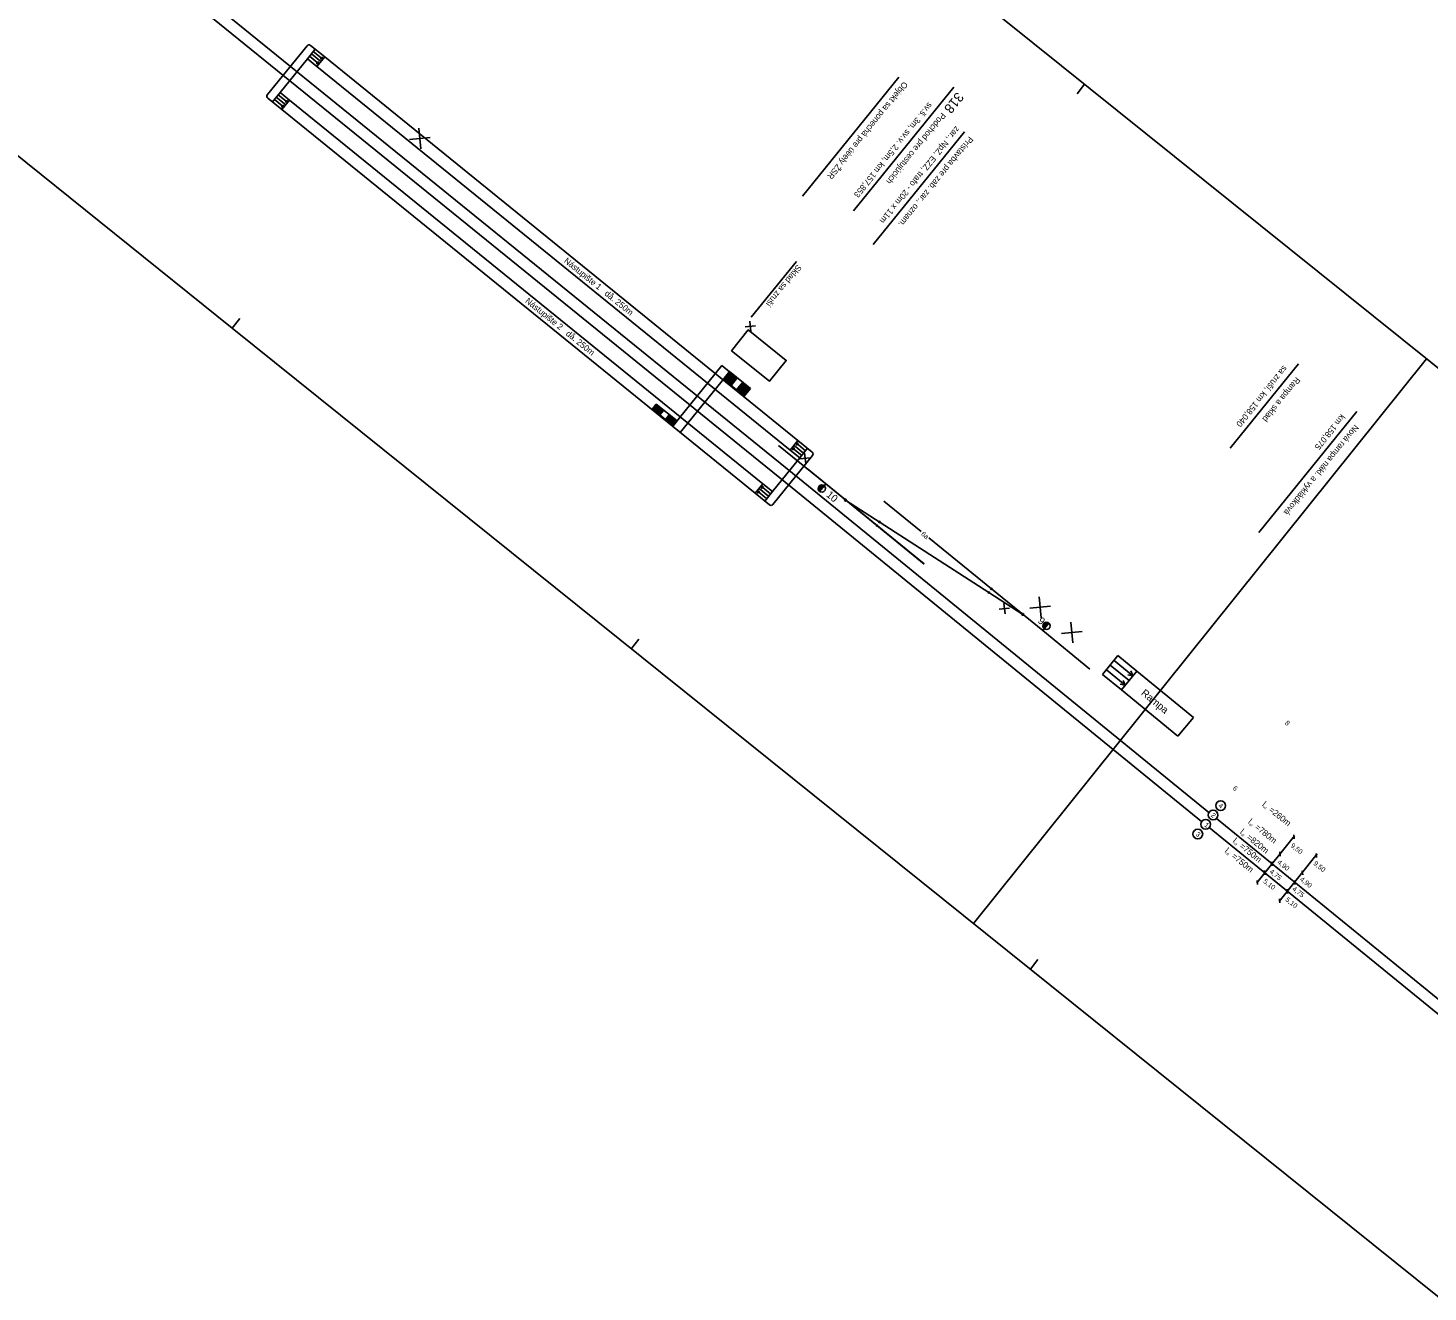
# Model space of a CAD drawing. Extents: x -486838 to -485015, y -1312876 to -1311330.
# Drawn here: x -486431 to -485856, y -1312351 to -1311833 of the extents above; entities that cross this region are included whole.
import ezdxf

# ---------------------------------------------------------------- set-up
doc = ezdxf.new("R2010")
doc.units = 0
for name, color, linetype in [('kolaj s', 7, 'Continuous'), ('Level 61', 7, 'Continuous'), ('popis 25', 7, 'Continuous'), ('popis 35', 7, 'Continuous'), ('stavby', 7, 'Continuous')]:
    doc.layers.add(name, color=color, linetype=linetype)

msp = doc.modelspace()

# ---------------------------------------------------------------- linework, layer by layer
at = {"layer": 'kolaj s'}
for p, q in [((-486420.89, -1311775.01), (-486117.19, -1312021.16)), ((-486417.9, -1311771.32), (-486114.2, -1312017.47)), ((-486122.79, -1312003.76), (-486103.41, -1312019.55)), ((-486110.85, -1312013.35), (-486062.97, -1312052.36)), ((-486117.2, -1312021.15), (-485949.13, -1312158.08)), ((-486114.2, -1312017.47), (-485946.15, -1312154.38)), ((-486103.41, -1312019.55), (-486082.37, -1312036.69)), ((-486095.25, -1312026.2), (-486095.25, -1312026.2)), ((-486095.25, -1312026.2), (-486036.48, -1312064.12)), ((-486079.6, -1312026.61), (-486064.23, -1312039.13)), ((-486082.05, -1312036.3), (-486082.69, -1312037.08)), ((-486082.37, -1312036.69), (-486082.37, -1312036.69)), ((-486082.37, -1312036.69), (-486063.03, -1312052.45)), ((-486081.02, -1312034.78), (-486081.56, -1312035.62)), ((-486081.29, -1312035.2), (-486081.29, -1312035.2)), ((-486061.14, -1312041.65), (-486035.39, -1312062.63)), ((-486035.71, -1312063.02), (-486035.08, -1312062.24)), ((-486014.35, -1312079.77), (-486035.39, -1312062.63)), ((-486035.39, -1312062.63), (-486035.39, -1312062.63)), ((-486036.75, -1312064.54), (-486036.2, -1312063.7)), ((-486022.51, -1312073.13), (-486036.48, -1312064.12)), ((-486036.48, -1312064.12), (-486036.48, -1312064.12)), ((-486022.51, -1312073.13), (-486022.51, -1312073.13)), ((-486014.35, -1312079.77), (-485994.97, -1312095.56)), ((-485946.04, -1312160.6), (-485775.23, -1312299.76)), ((-485943.07, -1312156.89), (-485716.4, -1312341.55))]:
    msp.add_line(p, q, dxfattribs=at)
for points in [[(-486094.94, -1312026.45), (-486095.32, -1312026.59), (-486095.62, -1312026.34), (-486095.56, -1312025.94), (-486095.19, -1312025.8), (-486094.88, -1312026.05), (-486094.94, -1312026.45)], [(-486022.82, -1312072.87), (-486022.45, -1312072.73), (-486022.14, -1312072.98), (-486022.2, -1312073.38), (-486022.58, -1312073.52), (-486022.89, -1312073.27), (-486022.82, -1312072.87)]]:
    msp.add_lwpolyline(points, dxfattribs=at)
at = {"layer": 'Level 61'}
for p, q in [((-486346.87, -1311955.63), (-486838.03, -1311561.1)), ((-486160.87, -1311724.08), (-485014.82, -1312644.65)), ((-485997.15, -1311855.59), (-486000.28, -1311859.49)), ((-486343.74, -1311951.73), (-486346.87, -1311955.63)), ((-485200.81, -1312876.2), (-486346.87, -1311955.63)), ((-485856.82, -1311968.31), (-486042.81, -1312199.86)), ((-486180.01, -1312083.24), (-486183.14, -1312087.14)), ((-486016.29, -1312214.75), (-486019.42, -1312218.65)), ((-486016.29, -1312214.75), (-486019.42, -1312218.65))]:
    msp.add_line(p, q, dxfattribs=at)
at = {"layer": 'popis 25'}
for p, q in [((-485910.98, -1312163.9), (-485926.56, -1312183.29)), ((-485911.18, -1312165.17), (-485911.37, -1312163.5)), ((-485901.67, -1312171.38), (-485917.31, -1312190.84)), ((-485916.93, -1312172.25), (-485917.12, -1312170.58)), ((-485901.95, -1312172.82), (-485902.14, -1312171.15)), ((-485920.19, -1312176.24), (-485920.39, -1312174.57)), ((-485926.22, -1312183.88), (-485926.41, -1312182.22)), ((-485923.09, -1312179.91), (-485923.28, -1312178.24)), ((-485910.91, -1312183.97), (-485911.1, -1312182.3)), ((-485907.68, -1312179.96), (-485907.88, -1312178.29)), ((-485913.91, -1312187.57), (-485914.11, -1312185.9)), ((-485917.02, -1312191.43), (-485917.21, -1312189.77))]:
    msp.add_line(p, q, dxfattribs=at)
at = {"layer": 'popis 35'}
for p, q in [((-486265.63, -1311877.43), (-486274.14, -1311878.26)), ((-486269.47, -1311882.1), (-486270.31, -1311873.59)), ((-486134.1, -1311957.03), (-486134.52, -1311952.78)), ((-486132.18, -1311954.7), (-486136.44, -1311955.12)), ((-486109.72, -1312008.84), (-486113.97, -1312009.31)), ((-486111.61, -1312011.2), (-486112.08, -1312006.95)), ((-486103.41, -1312019.55), (-486105.88, -1312022.63)), ((-486103.41, -1312019.55), (-486103.41, -1312019.55)), ((-486029.82, -1312072.88), (-486030.29, -1312068.63)), ((-486014.94, -1312074.45), (-486015.78, -1312065.94)), ((-486027.93, -1312070.53), (-486032.18, -1312070.99)), ((-486011.11, -1312069.77), (-486019.62, -1312070.61)), ((-486014.35, -1312079.77), (-486011.88, -1312076.69)), ((-486014.35, -1312079.77), (-486014.35, -1312079.77)), ((-485998.18, -1312080.16), (-486006.68, -1312081)), ((-486002.01, -1312084.83), (-486002.85, -1312076.33))]:
    msp.add_line(p, q, dxfattribs=at)
for points in [[(-486106.2, -1312022.38), (-486105.57, -1312022.88), (-486104.81, -1312022.99), (-486104.1, -1312022.72), (-486103.6, -1312022.1), (-486103.48, -1312021.34), (-486103.78, -1312020.59), (-486104.37, -1312020.13), (-486105.14, -1312020.01), (-486105.86, -1312020.28), (-486106.36, -1312020.9), (-486106.47, -1312021.66), (-486106.2, -1312022.38), (-486106.23, -1312022.03), (-486105.84, -1312022.34), (-486105.66, -1312022.11), (-486106.32, -1312021.57), (-486106.29, -1312021.22), (-486105.47, -1312021.87), (-486105.28, -1312021.64), (-486106.18, -1312020.92), (-486105.99, -1312020.68), (-486105.09, -1312021.41), (-486104.91, -1312021.17), (-486105.8, -1312020.45), (-486105.5, -1312020.31), (-486104.72, -1312020.94), (-486104.53, -1312020.7), (-486105.19, -1312020.17), (-486104.69, -1312020.19), (-486104.34, -1312020.47)], [(-486012.19, -1312076.44), (-486011.57, -1312076.94), (-486011.3, -1312077.69), (-486011.42, -1312078.43), (-486011.9, -1312079.03), (-486012.63, -1312079.31), (-486013.39, -1312079.2), (-486014.01, -1312078.7), (-486014.28, -1312077.99), (-486014.17, -1312077.23), (-486013.67, -1312076.6), (-486012.95, -1312076.33), (-486012.19, -1312076.44), (-486012.54, -1312076.48), (-486012.15, -1312076.79), (-486012.34, -1312077.03), (-486013.01, -1312076.5), (-486013.35, -1312076.6), (-486012.53, -1312077.26), (-486012.72, -1312077.5), (-486013.61, -1312076.78), (-486013.8, -1312077.01), (-486012.91, -1312077.73), (-486013.09, -1312077.96), (-486013.99, -1312077.24), (-486014.06, -1312077.57), (-486013.28, -1312078.2), (-486013.47, -1312078.43), (-486014.13, -1312077.9), (-486014.05, -1312078.35), (-486013.66, -1312078.66)]]:
    msp.add_lwpolyline(points, dxfattribs=at)
for centre in [(-485944.43, -1312155.42), (-485941.35, -1312151.57), (-485947.47, -1312159.2), (-485950.71, -1312163.23)]:
    msp.add_circle(centre, 2, dxfattribs=at)
at = {"layer": 'stavby'}
for p, q in [((-486332.48, -1311859.87), (-486316.21, -1311839.8)), ((-486316.01, -1311845.12), (-486312.87, -1311841.23)), ((-486311.34, -1311847.29), (-486315.23, -1311844.14)), ((-486314.81, -1311839.66), (-486308.98, -1311844.38)), ((-486310.56, -1311846.32), (-486314.44, -1311843.17)), ((-486309.77, -1311845.35), (-486313.65, -1311842.2)), ((-486312.13, -1311848.27), (-486308.98, -1311844.38)), ((-486308.98, -1311844.38), (-486312.13, -1311848.27)), ((-486310.2, -1311844.35), (-486309.77, -1311845.35)), ((-486308.98, -1311844.38), (-486114.78, -1312001.81)), ((-486327.24, -1311858.97), (-486316.01, -1311845.12)), ((-486312.13, -1311848.27), (-486316.01, -1311845.12)), ((-486312.41, -1311847.08), (-486311.34, -1311847.29)), ((-486117.93, -1312005.7), (-486312.13, -1311848.27)), ((-486311.77, -1311846.29), (-486311.34, -1311847.29)), ((-486310.84, -1311845.14), (-486309.77, -1311845.35)), ((-486112.98, -1311901.57), (-486073.32, -1311852.63)), ((-486326.51, -1311866), (-486332.33, -1311861.28)), ((-486330.39, -1311862.85), (-486327.24, -1311858.97)), ((-486325.72, -1311865.03), (-486329.6, -1311861.88)), ((-486324.93, -1311864.06), (-486328.82, -1311860.91)), ((-486324.15, -1311863.09), (-486328.03, -1311859.94)), ((-486327.24, -1311858.97), (-486323.36, -1311862.12)), ((-486091.93, -1311907.53), (-486050.78, -1311856.76)), ((-486326.79, -1311864.82), (-486325.72, -1311865.03)), ((-486326.51, -1311866), (-486323.36, -1311862.12)), ((-486323.36, -1311862.12), (-486326.51, -1311866)), ((-486132.3, -1312023.43), (-486326.51, -1311866)), ((-486326.15, -1311864.03), (-486325.72, -1311865.03)), ((-486325.21, -1311862.87), (-486324.15, -1311863.09)), ((-486324.57, -1311862.09), (-486324.15, -1311863.09)), ((-486323.36, -1311862.12), (-486129.15, -1312019.55)), ((-486083.91, -1311921.29), (-486046.47, -1311875.11)), ((-486133.94, -1311951.21), (-486115.34, -1311928.27)), ((-485937.46, -1312004.92), (-485909.46, -1311970.37)), ((-486166.19, -1311995.96), (-486145.98, -1311971.03)), ((-486163.08, -1311998.48), (-486142.88, -1311973.55)), ((-486142.88, -1311973.55), (-486145.98, -1311971.03)), ((-486145.36, -1311976.62), (-486142.84, -1311973.51)), ((-486136.8, -1311983.54), (-486145.36, -1311976.62)), ((-486144.97, -1311976.93), (-486142.45, -1311973.82)), ((-486144.58, -1311977.25), (-486142.06, -1311974.14)), ((-486144.19, -1311977.56), (-486141.67, -1311974.45)), ((-486143.8, -1311977.88), (-486141.29, -1311974.77)), ((-486143.41, -1311978.19), (-486140.9, -1311975.08)), ((-486143.02, -1311978.51), (-486140.51, -1311975.4)), ((-486142.84, -1311973.51), (-486134.29, -1311980.43)), ((-486142.64, -1311978.82), (-486140.12, -1311975.71)), ((-486142.25, -1311979.13), (-486139.73, -1311976.02)), ((-486137.46, -1311977.87), (-486139.98, -1311980.98)), ((-486137.07, -1311978.19), (-486139.59, -1311981.3)), ((-486136.68, -1311978.5), (-486139.2, -1311981.61)), ((-486136.29, -1311978.81), (-486138.81, -1311981.92)), ((-486135.9, -1311979.13), (-486138.42, -1311982.24)), ((-486135.52, -1311979.44), (-486138.03, -1311982.55)), ((-486135.13, -1311979.76), (-486137.64, -1311982.87)), ((-486134.74, -1311980.07), (-486137.25, -1311983.18)), ((-486134.29, -1311980.43), (-486136.8, -1311983.54)), ((-486174.52, -1311988.76), (-486172.95, -1311986.82)), ((-486174.13, -1311989.08), (-486172.56, -1311987.14)), ((-486173.74, -1311989.39), (-486172.17, -1311987.45)), ((-486173.35, -1311989.71), (-486171.78, -1311987.76)), ((-486172.96, -1311990.02), (-486171.39, -1311988.08)), ((-486172.95, -1311986.82), (-486164.39, -1311993.74)), ((-486165.97, -1311995.68), (-486174.52, -1311988.76)), ((-486172.58, -1311990.34), (-486171, -1311988.39)), ((-486172.19, -1311990.65), (-486170.61, -1311988.71)), ((-486171.8, -1311990.97), (-486170.23, -1311989.02)), ((-486171.41, -1311991.28), (-486169.84, -1311989.34)), ((-486167.56, -1311991.18), (-486169.14, -1311993.12)), ((-486167.17, -1311991.5), (-486168.75, -1311993.44)), ((-486166.79, -1311991.81), (-486168.36, -1311993.75)), ((-486166.4, -1311992.12), (-486167.97, -1311994.07)), ((-486166.01, -1311992.44), (-486167.58, -1311994.38)), ((-486165.62, -1311992.75), (-486167.19, -1311994.7)), ((-486165.23, -1311993.07), (-486166.8, -1311995.01)), ((-486164.84, -1311993.38), (-486166.41, -1311995.33)), ((-486164.39, -1311993.74), (-486165.97, -1311995.68)), ((-485925.73, -1312039.53), (-485885.47, -1311989.87)), ((-486114.78, -1312001.81), (-486117.93, -1312005.7)), ((-486117.93, -1312005.7), (-486114.78, -1312001.81)), ((-486117.14, -1312004.73), (-486113.25, -1312007.88)), ((-486116.71, -1312005.73), (-486117.14, -1312004.73)), ((-486116.07, -1312004.94), (-486117.14, -1312004.73)), ((-486116.35, -1312003.75), (-486112.47, -1312006.9)), ((-486115.56, -1312002.78), (-486111.68, -1312005.93)), ((-486115.14, -1312003.78), (-486115.56, -1312002.78)), ((-486114.5, -1312003), (-486115.56, -1312002.78)), ((-486114.78, -1312001.81), (-486108.95, -1312006.54)), ((-486110.89, -1312004.96), (-486114.04, -1312008.85)), ((-486125.27, -1312022.7), (-486114.04, -1312008.85)), ((-486125.07, -1312028.01), (-486108.81, -1312007.94)), ((-486114.04, -1312008.85), (-486117.93, -1312005.7)), ((-486129.15, -1312019.55), (-486132.3, -1312023.43)), ((-486132.3, -1312023.43), (-486129.15, -1312019.55)), ((-486131.52, -1312022.46), (-486127.63, -1312025.61)), ((-486131.09, -1312023.46), (-486131.52, -1312022.46)), ((-486130.45, -1312022.67), (-486131.52, -1312022.46)), ((-486130.73, -1312021.49), (-486126.84, -1312024.64)), ((-486129.94, -1312020.52), (-486126.06, -1312023.67)), ((-486129.51, -1312021.52), (-486129.94, -1312020.52)), ((-486128.87, -1312020.73), (-486129.94, -1312020.52)), ((-486129.15, -1312019.55), (-486125.27, -1312022.7)), ((-486125.27, -1312022.7), (-486128.42, -1312026.58)), ((-486126.48, -1312028.16), (-486132.3, -1312023.43)), ((-485989.81, -1312097.77), (-485983.48, -1312090.03)), ((-485983.48, -1312090.03), (-485975.74, -1312096.36)), ((-485980.49, -1312102.16), (-485988.23, -1312095.83)), ((-485978.91, -1312100.23), (-485986.65, -1312093.9)), ((-485977.32, -1312098.3), (-485985.06, -1312091.96)), ((-485975.74, -1312096.36), (-485982.07, -1312104.1)), ((-485978.17, -1312096.29), (-485977.32, -1312098.3)), ((-485975.74, -1312096.36), (-485952.52, -1312115.36)), ((-485982.07, -1312104.1), (-485989.81, -1312097.77)), ((-485982.62, -1312101.73), (-485980.49, -1312102.16)), ((-485981.34, -1312100.16), (-485980.49, -1312102.16)), ((-485979.45, -1312097.86), (-485977.32, -1312098.3)), ((-485982.07, -1312104.1), (-485958.86, -1312123.1)), ((-485952.52, -1312115.36), (-485958.86, -1312123.1))]:
    msp.add_line(p, q, dxfattribs=at)
msp.add_lwpolyline([(-486142.08, -1311964.96), (-486135.19, -1311956.38), (-486119.6, -1311968.91), (-486126.49, -1311977.48)], close=True, dxfattribs=at)
for centre, start, end in [((-486315.44, -1311840.43), 50.95992, 140.97633), ((-486331.7, -1311860.5), 140.96837, 230.96197), ((-486109.58, -1312007.31), 320.972, 50.96537), ((-486125.85, -1312027.38), 230.96723, 320.97492)]:
    msp.add_arc(centre, 1, start, end, dxfattribs=at)

# ---------------------------------------------------------------- texts
at = {"layer": 'popis 25'}
for s, height, rotation, p in [('l   =260m', 2.5, 321.22682, (-485924.52, -1312151.51)), ('už', 1, 321.22682, (-485924.1, -1312152.21)), ('l   =780m', 2.5, 321.22682, (-485930.3, -1312158.61)), ('už', 1, 321.22682, (-485929.83, -1312159.34)), ('l   =750m', 2.5, 321.22682, (-485936.57, -1312166.42)), ('l   =820m', 2.5, 321.22682, (-485933.63, -1312162.77)), ('už', 1, 321.22682, (-485933.17, -1312163.49)), ('l   =750m', 2.5, 321.22682, (-485939.86, -1312170.51)), ('už', 1, 321.22682, (-485939.39, -1312171.24)), ('už', 1, 321.22682, (-485936.1, -1312167.15)), ('9,50', 2, 321.62202, (-485912.85, -1312168.3)), ('4,90', 2, 321.62202, (-485918.29, -1312175.14)), ('9,50', 2, 321.62202, (-485903.49, -1312175.65)), ('5,10', 2, 321.62202, (-485924.06, -1312182.95)), ('4,75', 2, 321.62202, (-485921.49, -1312179.02)), ('4,90', 2, 321.62202, (-485909.04, -1312182.13)), ('5,10', 2, 321.62202, (-485914.96, -1312190.47)), ('4,75', 2, 321.62202, (-485912.19, -1312186.07))]:
    msp.add_text(s, height=height, rotation=rotation, dxfattribs=at).set_placement(p)
at = {"layer": 'popis 35'}
for s, height, rotation, p in [('Objekt sa ponechá pre úèely ŽSR', 2.5, 231.02682, (-486071.39, -1311854.3)), ('sv.š. 3m, sv.v. 2,5m, km 157,853', 2.5, 231.02682, (-486061.25, -1311862.82)), ('Podchod pre cestujúcich', 2.5, 231.02682, (-486055.83, -1311867.03)), ('zar., NpZ, EZZ, trafo - 20m x 11m', 2.5, 231.02682, (-486050.01, -1311872.61)), ('Prístavba pre zab. zar., oznam.', 2.5, 231.02682, (-486044.57, -1311876.8)), ('Nástupište 1   då. 250m', 2.5, 321.02682, (-486211.01, -1311928.46)), ('Sklad sa zruší', 2.5, 231.02682, (-486114.97, -1311929.36)), ('Nástupište 2   då. 250m', 2.5, 321.02682, (-486226.88, -1311944.9)), ('sa zruší, km 158,040', 2.5, 231.02682, (-485915.61, -1311970.8)), ('Rampa a sklad', 2.5, 231.02682, (-485910.37, -1311975.54)), ('km 158,075', 2.5, 231.02682, (-485891.98, -1311990.74)), ('Nová rampa nákl. a vykládková', 2.5, 231.02682, (-485886.39, -1311995.04)), ('10', 3, 320.62682, (-486103.4, -1312024.48)), ('6a', 2, 321.22682, (-486064.48, -1312040.44)), ('9', 3, 320.62682, (-486016.63, -1312076.24)), ('8', 2, 321.22682, (-485915.15, -1312117.99)), ('6', 2, 321.22682, (-485936.58, -1312144.75)), ('2', 2, 321.22682, (-485945.53, -1312155.82)), ('4', 2, 321.22682, (-485942.48, -1312151.95)), ('1', 2, 321.22682, (-485948.26, -1312159.85)), ('3', 2, 321.22682, (-485951.81, -1312163.64))]:
    msp.add_text(s, height=height, rotation=rotation, dxfattribs=at).set_placement(p)
at = {"layer": 'stavby'}
for s, height, rotation, p in [('318', 4, 231.22682, (-486049.49, -1311858.54)), ('Rampa', 3, 320.62682, (-485974.23, -1312105.83))]:
    msp.add_text(s, height=height, rotation=rotation, dxfattribs=at).set_placement(p)

doc.saveas('drawing.dxf')
